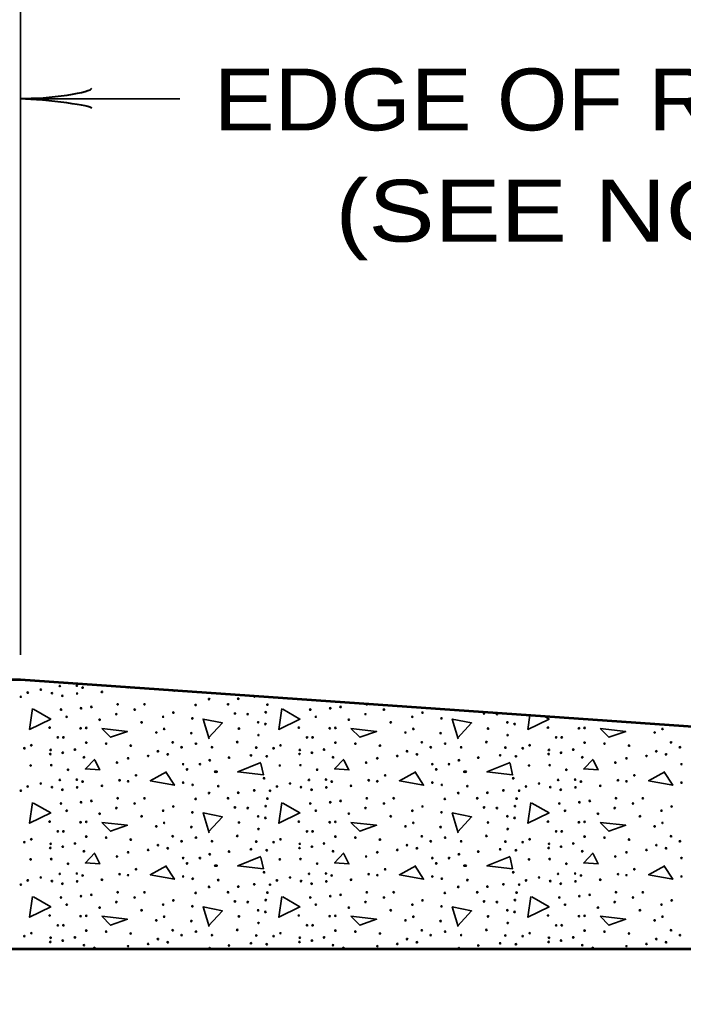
# Model space of a CAD drawing. Extents: x -105 to 751, y -65 to 479.
# Drawn here: x -4.86 to 27.37, y 278.79 to 326.17 of the extents above; entities that cross this region are included whole.
import ezdxf
from ezdxf.enums import TextEntityAlignment as Align

# ---------------------------------------------------------------- set-up
doc = ezdxf.new("R2010")
doc.units = 0
doc.header["$LTSCALE"] = 1.2
doc.layers.add('1', color=7, linetype='Continuous', lineweight=35)

msp = doc.modelspace()

# ---------------------------------------------------------------- linework, layer by layer
at = {"layer": '1'}
for p, q in [((-4.811, 295.325), (-4.811, 350.525)), ((-4.811, 322.325), (2.916, 322.325)), ((-1.206, 281.148), (-1.303, 281.046)), ((-1.179, 281.046), (-1.206, 281.1)), ((10.89, 281.148), (10.793, 281.046)), ((10.917, 281.046), (10.89, 281.1)), ((22.986, 281.148), (22.889, 281.046)), ((23.013, 281.046), (22.986, 281.1))]:
    msp.add_line(p, q, dxfattribs=at)
at = {"layer": '1', "lineweight": 53}
for points in [[(58.533, 316.446), (102.811, 316.446), (102.811, 359.646), (106.979, 363.962), (141.779, 363.962), (145.947, 359.646), (145.947, 281.046), (120.996, 281.046), (120.176, 278.791), (118.534, 283.301), (117.713, 281.046), (42.713, 281.046), (41.892, 278.791), (40.251, 283.301), (39.43, 281.046), (-6.77, 281.046), (-7.591, 278.791), (-9.232, 283.301), (-10.053, 281.046), (-27.453, 281.046), (-27.453, 285.944), (-29.708, 286.765), (-25.198, 288.406), (-27.453, 289.227)], [(-27.453, 289.227), (-27.453, 294.125), (-4.811, 294.125), (51.451, 290.19), (53.759, 312.148)]]:
    msp.add_lwpolyline(points, dxfattribs=at)
at = {"layer": '1'}
for points in [[(2.25, 293.631), (2.658, 293.556), (2.627, 293.605)], [(-4.182, 292.692), (-3.342, 292.212), (-4.374, 291.708), (-4.23, 292.716)], [(7.914, 292.692), (8.754, 292.212), (7.722, 291.708), (7.866, 292.716)], [(20.614, 292.347), (20.85, 292.212), (19.818, 291.708), (19.916, 292.396)], [(4.338, 291.252), (4.05, 292.212), (4.986, 292.02), (4.314, 291.3)], [(16.434, 291.252), (16.146, 292.212), (17.082, 292.02), (16.41, 291.3)], [(-1.206, 290.268), (-1.662, 289.788), (-0.966, 289.74), (-1.206, 290.22)], [(6.858, 290.1), (5.73, 289.644), (6.978, 289.5), (6.858, 290.052)], [(10.89, 290.268), (10.434, 289.788), (11.13, 289.74), (10.89, 290.22)], [(18.954, 290.1), (17.826, 289.644), (19.074, 289.5), (18.954, 290.052)], [(22.986, 290.268), (22.53, 289.788), (23.226, 289.74), (22.986, 290.22)], [(2.274, 289.644), (1.482, 289.212), (2.658, 288.996), (2.226, 289.668)], [(14.37, 289.644), (13.578, 289.212), (14.754, 288.996), (14.322, 289.668)], [(26.466, 289.644), (25.674, 289.212), (26.85, 288.996), (26.418, 289.668)], [(-4.182, 288.132), (-3.342, 287.652), (-4.374, 287.148), (-4.23, 288.156)], [(7.914, 288.132), (8.754, 287.652), (7.722, 287.148), (7.866, 288.156)], [(20.01, 288.132), (20.85, 287.652), (19.818, 287.148), (19.962, 288.156)], [(4.338, 286.692), (4.05, 287.652), (4.986, 287.46), (4.314, 286.74)], [(16.434, 286.692), (16.146, 287.652), (17.082, 287.46), (16.41, 286.74)], [(-1.206, 285.708), (-1.662, 285.228), (-0.966, 285.18), (-1.206, 285.66)], [(10.89, 285.708), (10.434, 285.228), (11.13, 285.18), (10.89, 285.66)], [(22.986, 285.708), (22.53, 285.228), (23.226, 285.18), (22.986, 285.66)], [(6.858, 285.54), (5.73, 285.084), (6.978, 284.94), (6.858, 285.492)], [(18.954, 285.54), (17.826, 285.084), (19.074, 284.94), (18.954, 285.492)], [(2.274, 285.084), (1.482, 284.652), (2.658, 284.436), (2.226, 285.108)], [(14.37, 285.084), (13.578, 284.652), (14.754, 284.436), (14.322, 285.108)], [(26.466, 285.084), (25.674, 284.652), (26.85, 284.436), (26.418, 285.108)], [(-4.182, 283.572), (-3.342, 283.092), (-4.374, 282.588), (-4.23, 283.596)], [(7.914, 283.572), (8.754, 283.092), (7.722, 282.588), (7.866, 283.596)], [(20.01, 283.572), (20.85, 283.092), (19.818, 282.588), (19.962, 283.596)], [(4.338, 282.132), (4.05, 283.092), (4.986, 282.9), (4.314, 282.18)], [(16.434, 282.132), (16.146, 283.092), (17.082, 282.9), (16.41, 282.18)]]:
    msp.add_lwpolyline(points, dxfattribs=at)
for points in [[(-0.87, 291.756), (0.378, 291.612), (-0.438, 291.324)], [(11.226, 291.756), (12.474, 291.612), (11.658, 291.324)], [(23.322, 291.756), (24.57, 291.612), (23.754, 291.324)], [(-0.87, 287.196), (0.378, 287.052), (-0.438, 286.764)], [(11.226, 287.196), (12.474, 287.052), (11.658, 286.764)], [(23.322, 287.196), (24.57, 287.052), (23.754, 286.764)], [(-0.87, 282.636), (0.378, 282.492), (-0.438, 282.204)], [(11.226, 282.636), (12.474, 282.492), (11.658, 282.204)], [(23.322, 282.636), (24.57, 282.492), (23.754, 282.204)]]:
    msp.add_lwpolyline(points, close=True, dxfattribs=at)
for centre in [(-2.906, 293.815), (-2.079, 293.831), (-1.799, 293.735), (-4.798, 293.29), (-4.464, 293.497), (-3.828, 293.64), (-3.287, 293.465), (-2.778, 293.338), (-2.063, 293.449), (-0.861, 293.528), (-1.37, 292.797), (-0.097, 292.924), (1.207, 292.924), (3.688, 292.892), (4.34, 293.179), (5.262, 292.924), (5.755, 293.194), (7.171, 292.908), (10.726, 292.797), (-2.842, 292.669), (-2.572, 292.319), (-1.872, 292.733), (-0.161, 292.447), (0.73, 292.669), (2.113, 292.319), (2.606, 292.526), (5.596, 292.479), (6.216, 292.447), (7.091, 292.542), (9.254, 292.669), (9.524, 292.319), (10.224, 292.733), (11.935, 292.447), (12.826, 292.669), (14.209, 292.319), (14.702, 292.526), (17.692, 292.479), (18.312, 292.447), (-0.972, 292.176), (1.064, 292.049), (3.529, 292.24), (6.725, 292.049), (7.075, 291.969), (11.124, 292.176), (13.16, 292.049), (15.625, 292.24), (18.821, 292.049), (19.171, 291.969), (-3.399, 291.794), (-1.896, 291.76), (-1.624, 291.779), (1.779, 291.556), (2.161, 291.731), (3.481, 291.524), (5.787, 291.747), (6.741, 291.429), (8.697, 291.794), (10.2, 291.76), (10.472, 291.779), (13.875, 291.556), (14.257, 291.731), (15.577, 291.524), (17.883, 291.747), (18.837, 291.429), (20.793, 291.794), (22.296, 291.76), (22.568, 291.779), (25.971, 291.556), (26.353, 291.731), (-4.289, 290.935), (-3.001, 291.317), (-2.731, 291.317), (-1.624, 291.063), (-0.654, 291.015), (0.539, 290.919), (2.574, 291.079), (3.704, 291.015), (5.707, 291.094), (7.807, 290.935), (9.095, 291.317), (9.365, 291.317), (10.472, 291.063), (11.442, 291.015), (12.635, 290.919), (14.67, 291.079), (15.8, 291.015), (17.803, 291.094), (19.903, 290.935), (21.191, 291.317), (21.461, 291.317), (22.568, 291.063), (23.538, 291.015), (24.731, 290.919), (26.766, 291.079), (-4.623, 290.792), (-3.367, 290.512), (-3.351, 290.713), (-2.763, 290.575), (-2.174, 290.729), (1.382, 290.416), (1.859, 290.649), (2.336, 290.496), (3.004, 290.84), (4.483, 290.84), (6.375, 290.448), (6.63, 290.824), (7.139, 290.4), (7.473, 290.792), (8.729, 290.512), (8.745, 290.713), (9.333, 290.575), (9.922, 290.729), (13.478, 290.416), (13.955, 290.649), (14.432, 290.496), (15.1, 290.84), (16.579, 290.84), (18.471, 290.448), (18.726, 290.824), (19.235, 290.4), (19.569, 290.792), (20.825, 290.512), (20.841, 290.713), (21.429, 290.575), (22.018, 290.729), (25.574, 290.416), (26.051, 290.649), (26.528, 290.496), (27.196, 290.84), (-4.321, 289.955), (-3.319, 289.971), (-1.735, 290.353), (-0.129, 290.098), (0.412, 290.305), (3.083, 290.019), (3.894, 290.019), (4.372, 290.209), (5.31, 290.337), (7.775, 289.955), (8.777, 289.971), (10.361, 290.353), (11.967, 290.098), (12.508, 290.305), (15.179, 290.019), (15.99, 290.019), (16.468, 290.209), (17.406, 290.337), (19.871, 289.955), (20.873, 289.971), (22.457, 290.353), (24.063, 290.098), (24.604, 290.305), (27.275, 290.019), (-2.508, 289.748), (0.793, 289.478), (3.274, 289.764), (4.642, 289.653), (4.706, 289.653), (9.588, 289.748), (12.889, 289.478), (15.37, 289.764), (16.738, 289.653), (16.802, 289.653), (21.684, 289.748), (24.985, 289.478), (-3.828, 289.08), (-2.906, 289.255), (-2.079, 289.271), (-1.799, 289.175), (-0.861, 288.968), (-0.002, 289.239), (0.412, 289.191), (3.083, 289.128), (3.545, 289.016), (7.012, 289.334), (8.268, 289.08), (9.19, 289.255), (10.017, 289.271), (10.297, 289.175), (11.235, 288.968), (12.094, 289.239), (12.508, 289.191), (15.179, 289.128), (15.641, 289.016), (19.108, 289.334), (20.364, 289.08), (21.286, 289.255), (22.113, 289.271), (22.393, 289.175), (23.331, 288.968), (24.19, 289.239), (24.604, 289.191), (27.275, 289.128), (-4.798, 288.73), (-4.464, 288.937), (-3.287, 288.905), (-2.778, 288.778), (-2.063, 288.889), (4.34, 288.619), (4.785, 288.953), (5.755, 288.634), (6.534, 288.746), (7.298, 288.73), (7.632, 288.937), (8.809, 288.905), (9.318, 288.778), (10.033, 288.889), (16.436, 288.619), (16.881, 288.953), (17.851, 288.634), (18.63, 288.746), (19.394, 288.73), (19.728, 288.937), (20.905, 288.905), (21.414, 288.778), (22.129, 288.889), (-2.842, 288.109), (-1.872, 288.173), (-1.37, 288.237), (-0.097, 288.364), (0.73, 288.109), (1.207, 288.364), (3.688, 288.332), (5.262, 288.364), (7.171, 288.348), (9.254, 288.109), (10.224, 288.173), (10.726, 288.237), (11.999, 288.364), (12.826, 288.109), (13.303, 288.364), (15.784, 288.332), (17.358, 288.364), (19.267, 288.348), (21.35, 288.109), (22.32, 288.173), (22.822, 288.237), (24.095, 288.364), (24.922, 288.109), (25.399, 288.364), (-2.572, 287.759), (-0.972, 287.616), (-0.161, 287.887), (2.113, 287.759), (2.606, 287.966), (3.529, 287.68), (5.596, 287.919), (6.216, 287.887), (7.091, 287.982), (9.524, 287.759), (11.124, 287.616), (11.935, 287.887), (14.209, 287.759), (14.702, 287.966), (15.625, 287.68), (17.692, 287.919), (18.312, 287.887), (19.187, 287.982), (21.62, 287.759), (23.22, 287.616), (24.031, 287.887), (26.305, 287.759), (26.798, 287.966), (-3.399, 287.234), (-1.896, 287.2), (-1.624, 287.219), (1.064, 287.489), (2.161, 287.171), (5.787, 287.187), (6.725, 287.489), (7.075, 287.409), (8.697, 287.234), (10.2, 287.2), (10.472, 287.219), (13.16, 287.489), (14.257, 287.171), (17.883, 287.187), (18.821, 287.489), (19.171, 287.409), (20.793, 287.234), (22.296, 287.2), (22.568, 287.219), (25.256, 287.489), (26.353, 287.171), (-3.001, 286.757), (-2.731, 286.757), (1.779, 286.996), (3.481, 286.964), (6.741, 286.869), (9.095, 286.757), (9.365, 286.757), (13.875, 286.996), (15.577, 286.964), (18.837, 286.869), (21.191, 286.757), (21.461, 286.757), (25.971, 286.996), (-4.623, 286.232), (-4.289, 286.375), (-3.351, 286.153), (-2.174, 286.169), (-1.624, 286.503), (-0.654, 286.455), (0.539, 286.359), (2.574, 286.519), (3.004, 286.28), (3.704, 286.455), (4.483, 286.28), (5.707, 286.534), (6.63, 286.264), (7.473, 286.232), (7.807, 286.375), (8.745, 286.153), (9.922, 286.169), (10.472, 286.503), (11.442, 286.455), (12.635, 286.359), (14.67, 286.519), (15.1, 286.28), (15.8, 286.455), (16.579, 286.28), (17.803, 286.534), (18.726, 286.264), (19.569, 286.232), (19.903, 286.375), (20.841, 286.153), (22.018, 286.169), (22.568, 286.503), (23.538, 286.455), (24.731, 286.359), (26.766, 286.519), (27.196, 286.28), (-3.367, 285.952), (-2.763, 286.015), (-1.735, 285.793), (0.412, 285.745), (1.382, 285.856), (1.859, 286.089), (2.336, 285.936), (5.31, 285.777), (6.375, 285.888), (7.139, 285.84), (8.729, 285.952), (9.333, 286.015), (10.361, 285.793), (12.508, 285.745), (13.478, 285.856), (13.955, 286.089), (14.432, 285.936), (17.406, 285.777), (18.471, 285.888), (19.235, 285.84), (20.825, 285.952), (21.429, 286.015), (22.457, 285.793), (24.604, 285.745), (25.574, 285.856), (26.051, 286.089), (26.528, 285.936), (-4.321, 285.395), (-3.319, 285.411), (-2.508, 285.188), (-0.129, 285.538), (3.083, 285.459), (3.274, 285.204), (3.894, 285.459), (4.372, 285.649), (7.775, 285.395), (8.777, 285.411), (9.588, 285.188), (11.967, 285.538), (15.179, 285.459), (15.37, 285.204), (15.99, 285.459), (16.468, 285.649), (19.871, 285.395), (20.873, 285.411), (21.684, 285.188), (24.063, 285.538), (27.275, 285.459), (-2.079, 284.711), (0.793, 284.918), (4.642, 285.093), (4.706, 285.093), (7.012, 284.774), (10.017, 284.711), (12.889, 284.918), (16.738, 285.093), (16.802, 285.093), (19.108, 284.774), (22.113, 284.711), (24.985, 284.918), (-4.464, 284.377), (-3.828, 284.52), (-3.287, 284.345), (-2.906, 284.695), (-2.063, 284.329), (-1.799, 284.615), (-0.861, 284.408), (-0.002, 284.679), (0.412, 284.631), (3.083, 284.568), (3.545, 284.456), (4.785, 284.393), (7.632, 284.377), (8.268, 284.52), (8.809, 284.345), (9.19, 284.695), (10.033, 284.329), (10.297, 284.615), (11.235, 284.408), (12.094, 284.679), (12.508, 284.631), (15.179, 284.568), (15.641, 284.456), (16.881, 284.393), (19.728, 284.377), (20.364, 284.52), (20.905, 284.345), (21.286, 284.695), (22.129, 284.329), (22.393, 284.615), (23.331, 284.408), (24.19, 284.679), (24.604, 284.631), (27.275, 284.568), (-4.798, 284.17), (-2.778, 284.218), (-0.097, 283.804), (1.207, 283.804), (3.688, 283.772), (4.34, 284.059), (5.262, 283.804), (5.755, 284.074), (6.534, 284.186), (7.171, 283.788), (7.298, 284.17), (9.318, 284.218), (11.999, 283.804), (13.303, 283.804), (15.784, 283.772), (16.436, 284.059), (17.358, 283.804), (17.851, 284.074), (18.63, 284.186), (19.267, 283.788), (19.394, 284.17), (21.414, 284.218), (24.095, 283.804), (25.399, 283.804), (-2.842, 283.549), (-1.872, 283.613), (-1.37, 283.677), (-0.161, 283.327), (0.73, 283.549), (2.606, 283.406), (5.596, 283.359), (6.216, 283.327), (7.091, 283.422), (9.254, 283.549), (10.224, 283.613), (10.726, 283.677), (11.935, 283.327), (12.826, 283.549), (14.702, 283.406), (17.692, 283.359), (18.312, 283.327), (19.187, 283.422), (21.35, 283.549), (22.32, 283.613), (22.822, 283.677), (24.031, 283.327), (24.922, 283.549), (26.798, 283.406), (-2.572, 283.199), (-0.972, 283.056), (1.064, 282.929), (2.113, 283.199), (3.529, 283.12), (6.725, 282.929), (7.075, 282.849), (9.524, 283.199), (11.124, 283.056), (13.16, 282.929), (14.209, 283.199), (15.625, 283.12), (18.821, 282.929), (19.171, 282.849), (21.62, 283.199), (23.22, 283.056), (25.256, 282.929), (26.305, 283.199), (-3.399, 282.674), (-1.896, 282.64), (-1.624, 282.659), (1.779, 282.436), (2.161, 282.611), (3.481, 282.404), (5.787, 282.627), (8.697, 282.674), (10.2, 282.64), (10.472, 282.659), (13.875, 282.436), (14.257, 282.611), (15.577, 282.404), (17.883, 282.627), (20.793, 282.674), (22.296, 282.64), (22.568, 282.659), (25.971, 282.436), (26.353, 282.611), (-3.001, 282.197), (-2.731, 282.197), (-1.624, 281.943), (-0.654, 281.895), (2.574, 281.959), (3.704, 281.895), (5.707, 281.974), (6.741, 282.309), (9.095, 282.197), (9.365, 282.197), (10.472, 281.943), (11.442, 281.895), (14.67, 281.959), (15.8, 281.895), (17.803, 281.974), (18.837, 282.309), (21.191, 282.197), (21.461, 282.197), (22.568, 281.943), (23.538, 281.895), (26.766, 281.959), (-4.623, 281.672), (-4.289, 281.815), (-3.367, 281.392), (-3.351, 281.593), (-2.763, 281.455), (-2.174, 281.609), (0.539, 281.799), (1.859, 281.529), (3.004, 281.72), (4.483, 281.72), (6.63, 281.704), (7.473, 281.672), (7.807, 281.815), (8.729, 281.392), (8.745, 281.593), (9.333, 281.455), (9.922, 281.609), (12.635, 281.799), (13.955, 281.529), (15.1, 281.72), (16.579, 281.72), (18.726, 281.704), (19.569, 281.672), (19.903, 281.815), (20.825, 281.392), (20.841, 281.593), (21.429, 281.455), (22.018, 281.609), (24.731, 281.799), (26.051, 281.529), (27.196, 281.72), (-1.735, 281.233), (0.412, 281.185), (1.382, 281.296), (2.336, 281.376), (4.372, 281.089), (5.31, 281.217), (6.375, 281.328), (7.139, 281.28), (10.361, 281.233), (12.508, 281.185), (13.478, 281.296), (14.432, 281.376), (16.468, 281.089), (17.406, 281.217), (18.471, 281.328), (19.235, 281.28), (22.457, 281.233), (24.604, 281.185), (25.574, 281.296), (26.528, 281.376)]:
    msp.add_circle(centre, 0.0318, dxfattribs=at)
for centre, start, end in [((-0.002, 293.799), 195.1395, 336.8604), ((0.412, 293.751), 160.8441, 11.1558), ((6.534, 293.306), 122.4633, 49.5367), ((7.298, 293.29), 197.8665, 334.1334), ((11.999, 292.924), 123.2369, 48.763), ((23.22, 292.176), 197.3844, 334.6155), ((25.256, 292.049), 232.8322, 299.1677)]:
    msp.add_arc(centre, 0.0318, start, end, dxfattribs=at)
at = {"layer": '1', "lineweight": 40}
for centre, major_axis, ratio, start_param, end_param in [((-3.502, 322.656), (-2.143, -0.187), 0.122415, 0.896353, 3.141593), ((-3.467, 322.071), (-2.108, 0.211), 0.07063, 3.140715, 5.41811)]:
    msp.add_ellipse(centre, major_axis=major_axis, ratio=ratio, start_param=start_param, end_param=end_param, dxfattribs=at)

# ---------------------------------------------------------------- texts
at = {"layer": '1'}
for s, width, p in [('EDGE OF ROADWAY', 1.1, (26.521, 320.787)), ('(SEE NOTE A)', 1.2, (26.521, 315.387))]:
    msp.add_text(s, height=3, dxfattribs=dict(at, width=width)).set_placement(p, align=Align.CENTER)

doc.saveas('drawing.dxf')
